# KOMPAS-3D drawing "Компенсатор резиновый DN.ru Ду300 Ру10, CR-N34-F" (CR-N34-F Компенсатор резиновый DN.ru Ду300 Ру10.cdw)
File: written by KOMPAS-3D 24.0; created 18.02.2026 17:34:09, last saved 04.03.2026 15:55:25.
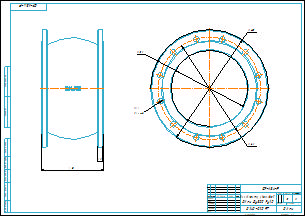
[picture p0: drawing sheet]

Document properties: Типовые: Типовые; Автор: DN.RU; Форматы листов документа: A2; Полное имя файла: CR-N34-F Компенсатор резиновый DN.ru Ду300 Ру10.m3d; Масса: 30; Наименование: Компенсатор резиновый DN.ru Ду300 Ру10; Количество листов документа: 1; Комментарий: D140-02097; Примечание: D140-02097

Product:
- Body: Твердое тело2  | qty 1
    Масса: 97.65083
- Part/product: Компенсатор резиновый DN.ru Ду300 Ру10  | designation CR-N34-F
    Масса: 30
    Раздел спецификации: Прочие изделия
    Комментарий: D140-02097
    Примечание: D140-02097
    additional columns: Типовые

Views: Вид 1, Спереди, Проекционный вид 2
Referenced files in E:\Работа\Зайцев\CR-N34-F Компенсатор резиновый DN.ru ДУ25-300 Ру10-16\DN300_PN10\: CR-N34-F Компенсатор резиновый DN.ru Ду300 Ру10.m3d
Referenced files in E:\Работа\Зайцев\Для компаса\: чертеж DN.ru А3.cdt
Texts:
  CR-N34-F
  чертеж DN.ru А3.cdt
  Компенсатор резиновый
  DN.ru Ду300 Ру10
  Твердое тело2
  Компенсатор резиновый DN.ru Ду300 Ру10
  CR-N34-F Компенсатор резиновый DN.ru Ду300 Ру10
Dimensions and other numbers on the sheet: 0; 3; 2; 4; 245; 21; 460; 400; 300; 22; 12 отв.; 1:2; 1; 30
